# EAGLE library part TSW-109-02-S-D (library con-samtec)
THROUGH-HOLE .025" SQ POST HEADER Source: Samtec TSW.pdf
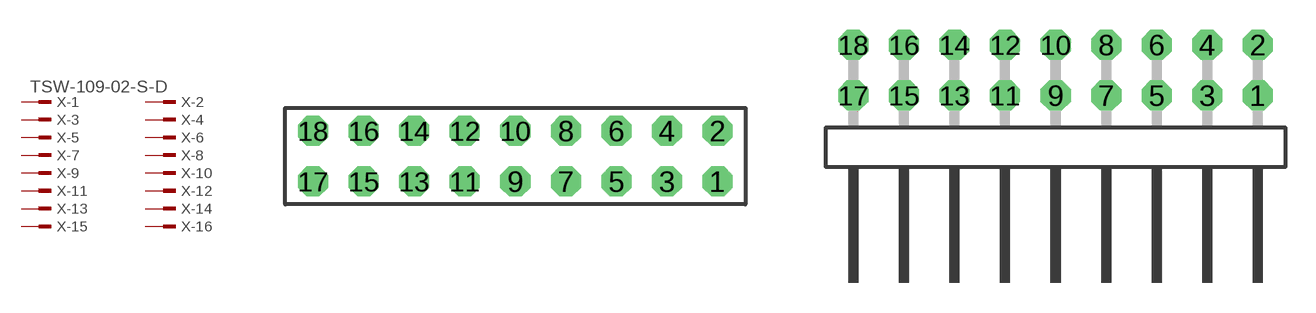
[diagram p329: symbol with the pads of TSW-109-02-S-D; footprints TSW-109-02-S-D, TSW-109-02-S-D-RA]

Designator prefix X; gates -1=MPINV -2=MPIN -3=MPIN -4=MPIN -5=MPIN -6=MPIN -7=MPIN -8=MPIN -9=MPIN -10=MPIN -11=MPIN -12=MPIN -13=MPIN -14=MPIN -15=MPIN -16=MPIN -17=MPIN -18=MPIN

## TSW-109-02-S-D (OC_FARNELL: unknown; OC_NEWARK: unknown)  [TSW-109-02-S-D]
1  -1:1  pas
2  -2:1  pas
3  -3:1  pas
4  -4:1  pas
5  -5:1  pas
6  -6:1  pas
7  -7:1  pas
8  -8:1  pas
9  -9:1  pas
10  -10:1  pas
11  -11:1  pas
12  -12:1  pas
13  -13:1  pas
14  -14:1  pas
15  -15:1  pas
16  -16:1  pas
17  -17:1  pas
18  -18:1  pas

## TSW-109-02-S-D-RA (OC_FARNELL: unknown; OC_NEWARK: unknown)  [TSW-109-02-S-D-RA]
Pads as for TSW-109-02-S-D

## Footprint TSW-109-02-S-D (pad centres in mm)
THROUGH-HOLE .025" SQ POST HEADER Source: Samtec TSW.pdf
drill 1 pad 1.5 octagon: 1 10.16,-1.27; 2 10.16,1.27; 3 7.62,-1.27; 4 7.62,1.27; 5 5.08,-1.27; 6 5.08,1.27; 7 2.54,-1.27; 8 2.54,1.27; 9 0,-1.27; 10 0,1.27; 11 -2.54,-1.27; 12 -2.54,1.27; 13 -5.08,-1.27; 14 -5.08,1.27; 15 -7.62,-1.27; 16 -7.62,1.27; 17 -10.16,-1.27; 18 -10.16,1.27

## Footprint TSW-109-02-S-D-RA (pad centres in mm)
THROUGH-HOLE .025" SQ POST HEADER Source: Samtec TSW.pdf
drill 1 pad 1.5 octagon: 1 10.16,1.524; 2 10.16,4.064; 3 7.62,1.524; 4 7.62,4.064; 5 5.08,1.524; 6 5.08,4.064; 7 2.54,1.524; 8 2.54,4.064; 9 0,1.524; 10 0,4.064; 11 -2.54,1.524; 12 -2.54,4.064; 13 -5.08,1.524; 14 -5.08,4.064; 15 -7.62,1.524; 16 -7.62,4.064; 17 -10.16,1.524; 18 -10.16,4.064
